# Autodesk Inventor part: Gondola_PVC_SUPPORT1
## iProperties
Shininess: 64.0
Length Units: 11272
Angle Units: 11279
Time Units: 11290
Mass Units: 11286
Length Display Precision: 3
Angle Display Precision: 2
Compacted: True
Part Number: Gondola_PVC_SUPPORT1
Document SubType Name: Modeling
Created: 2004-08
Designer: John Blackburn
Manufacturer: Standard
Standards Organization: Custom
Material: PVC-Piping
Density: 0.0
Volumn: 0.0
Area: 0.0
PropertySet Name: Model Information
Control State: 0
Master: False
Checked Out: False
Author: John Blackburn
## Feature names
1. Base1
